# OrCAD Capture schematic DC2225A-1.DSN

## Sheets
1 PAGE3: size Custom; title: HIGH EFFICIENCY, SINGLE-OUTPUT SYNCHRONOUS BUCK; rev: 1; company: TM
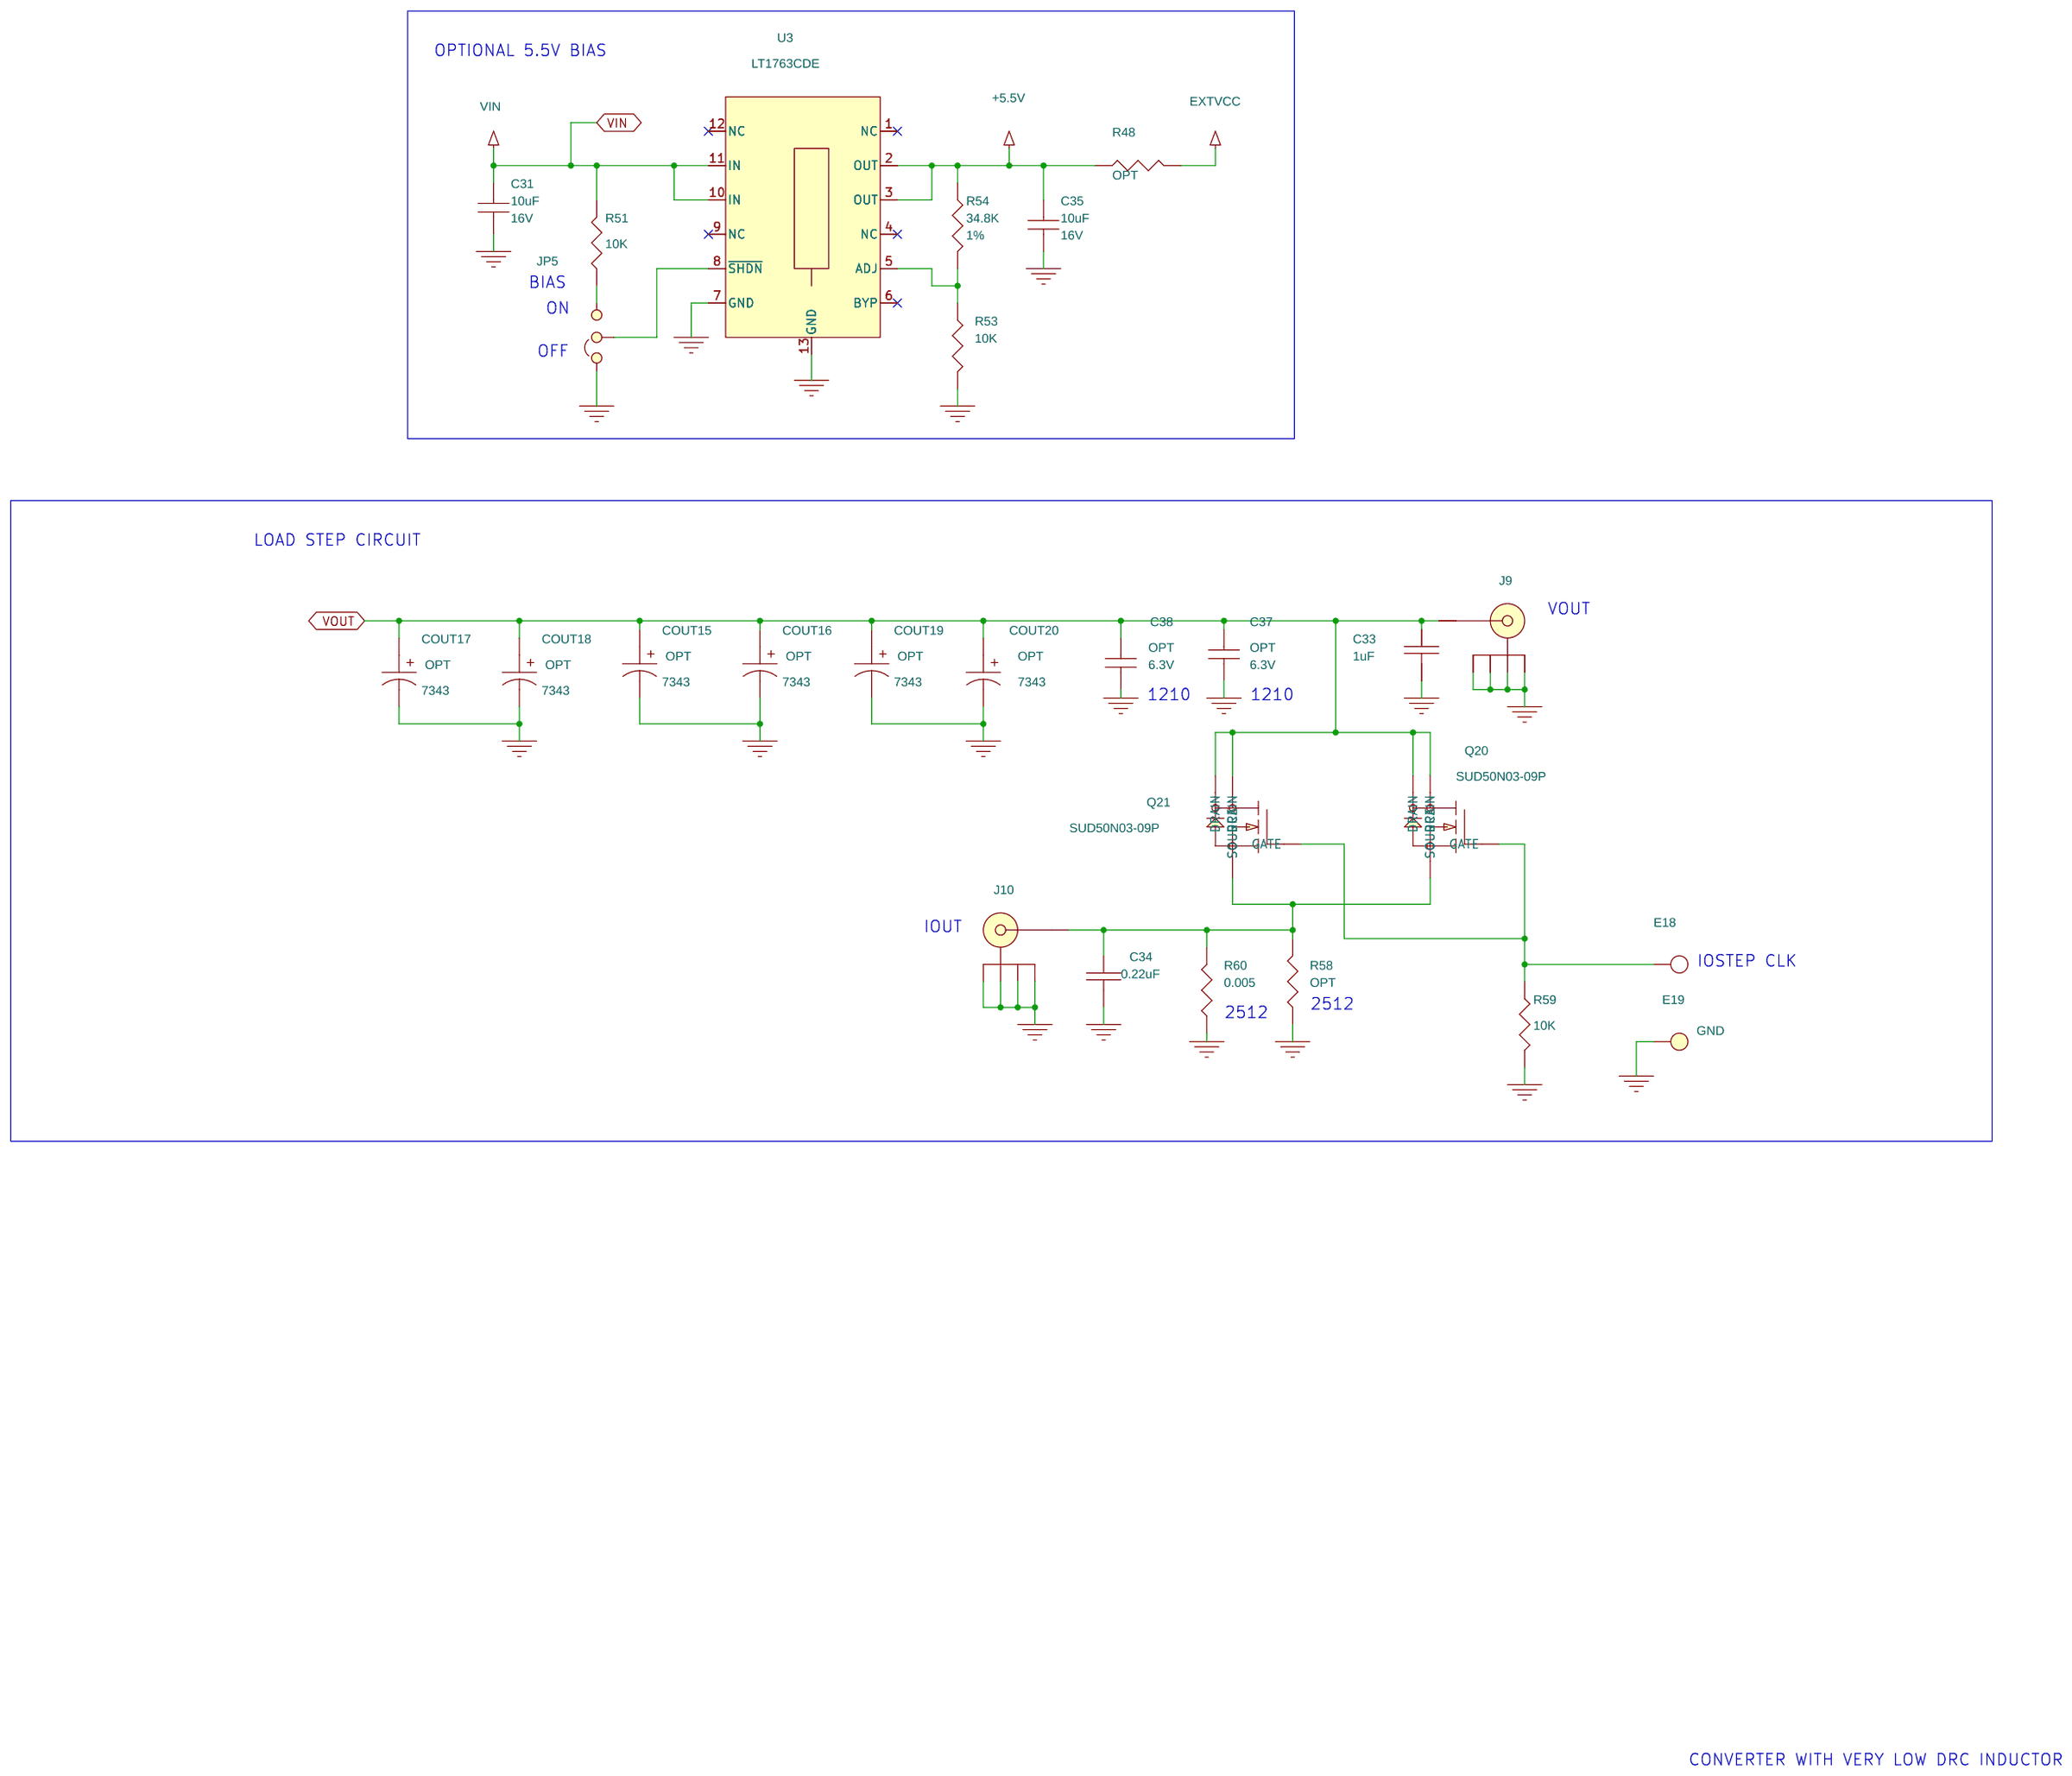
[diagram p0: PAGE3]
2 PAGE2: size Custom
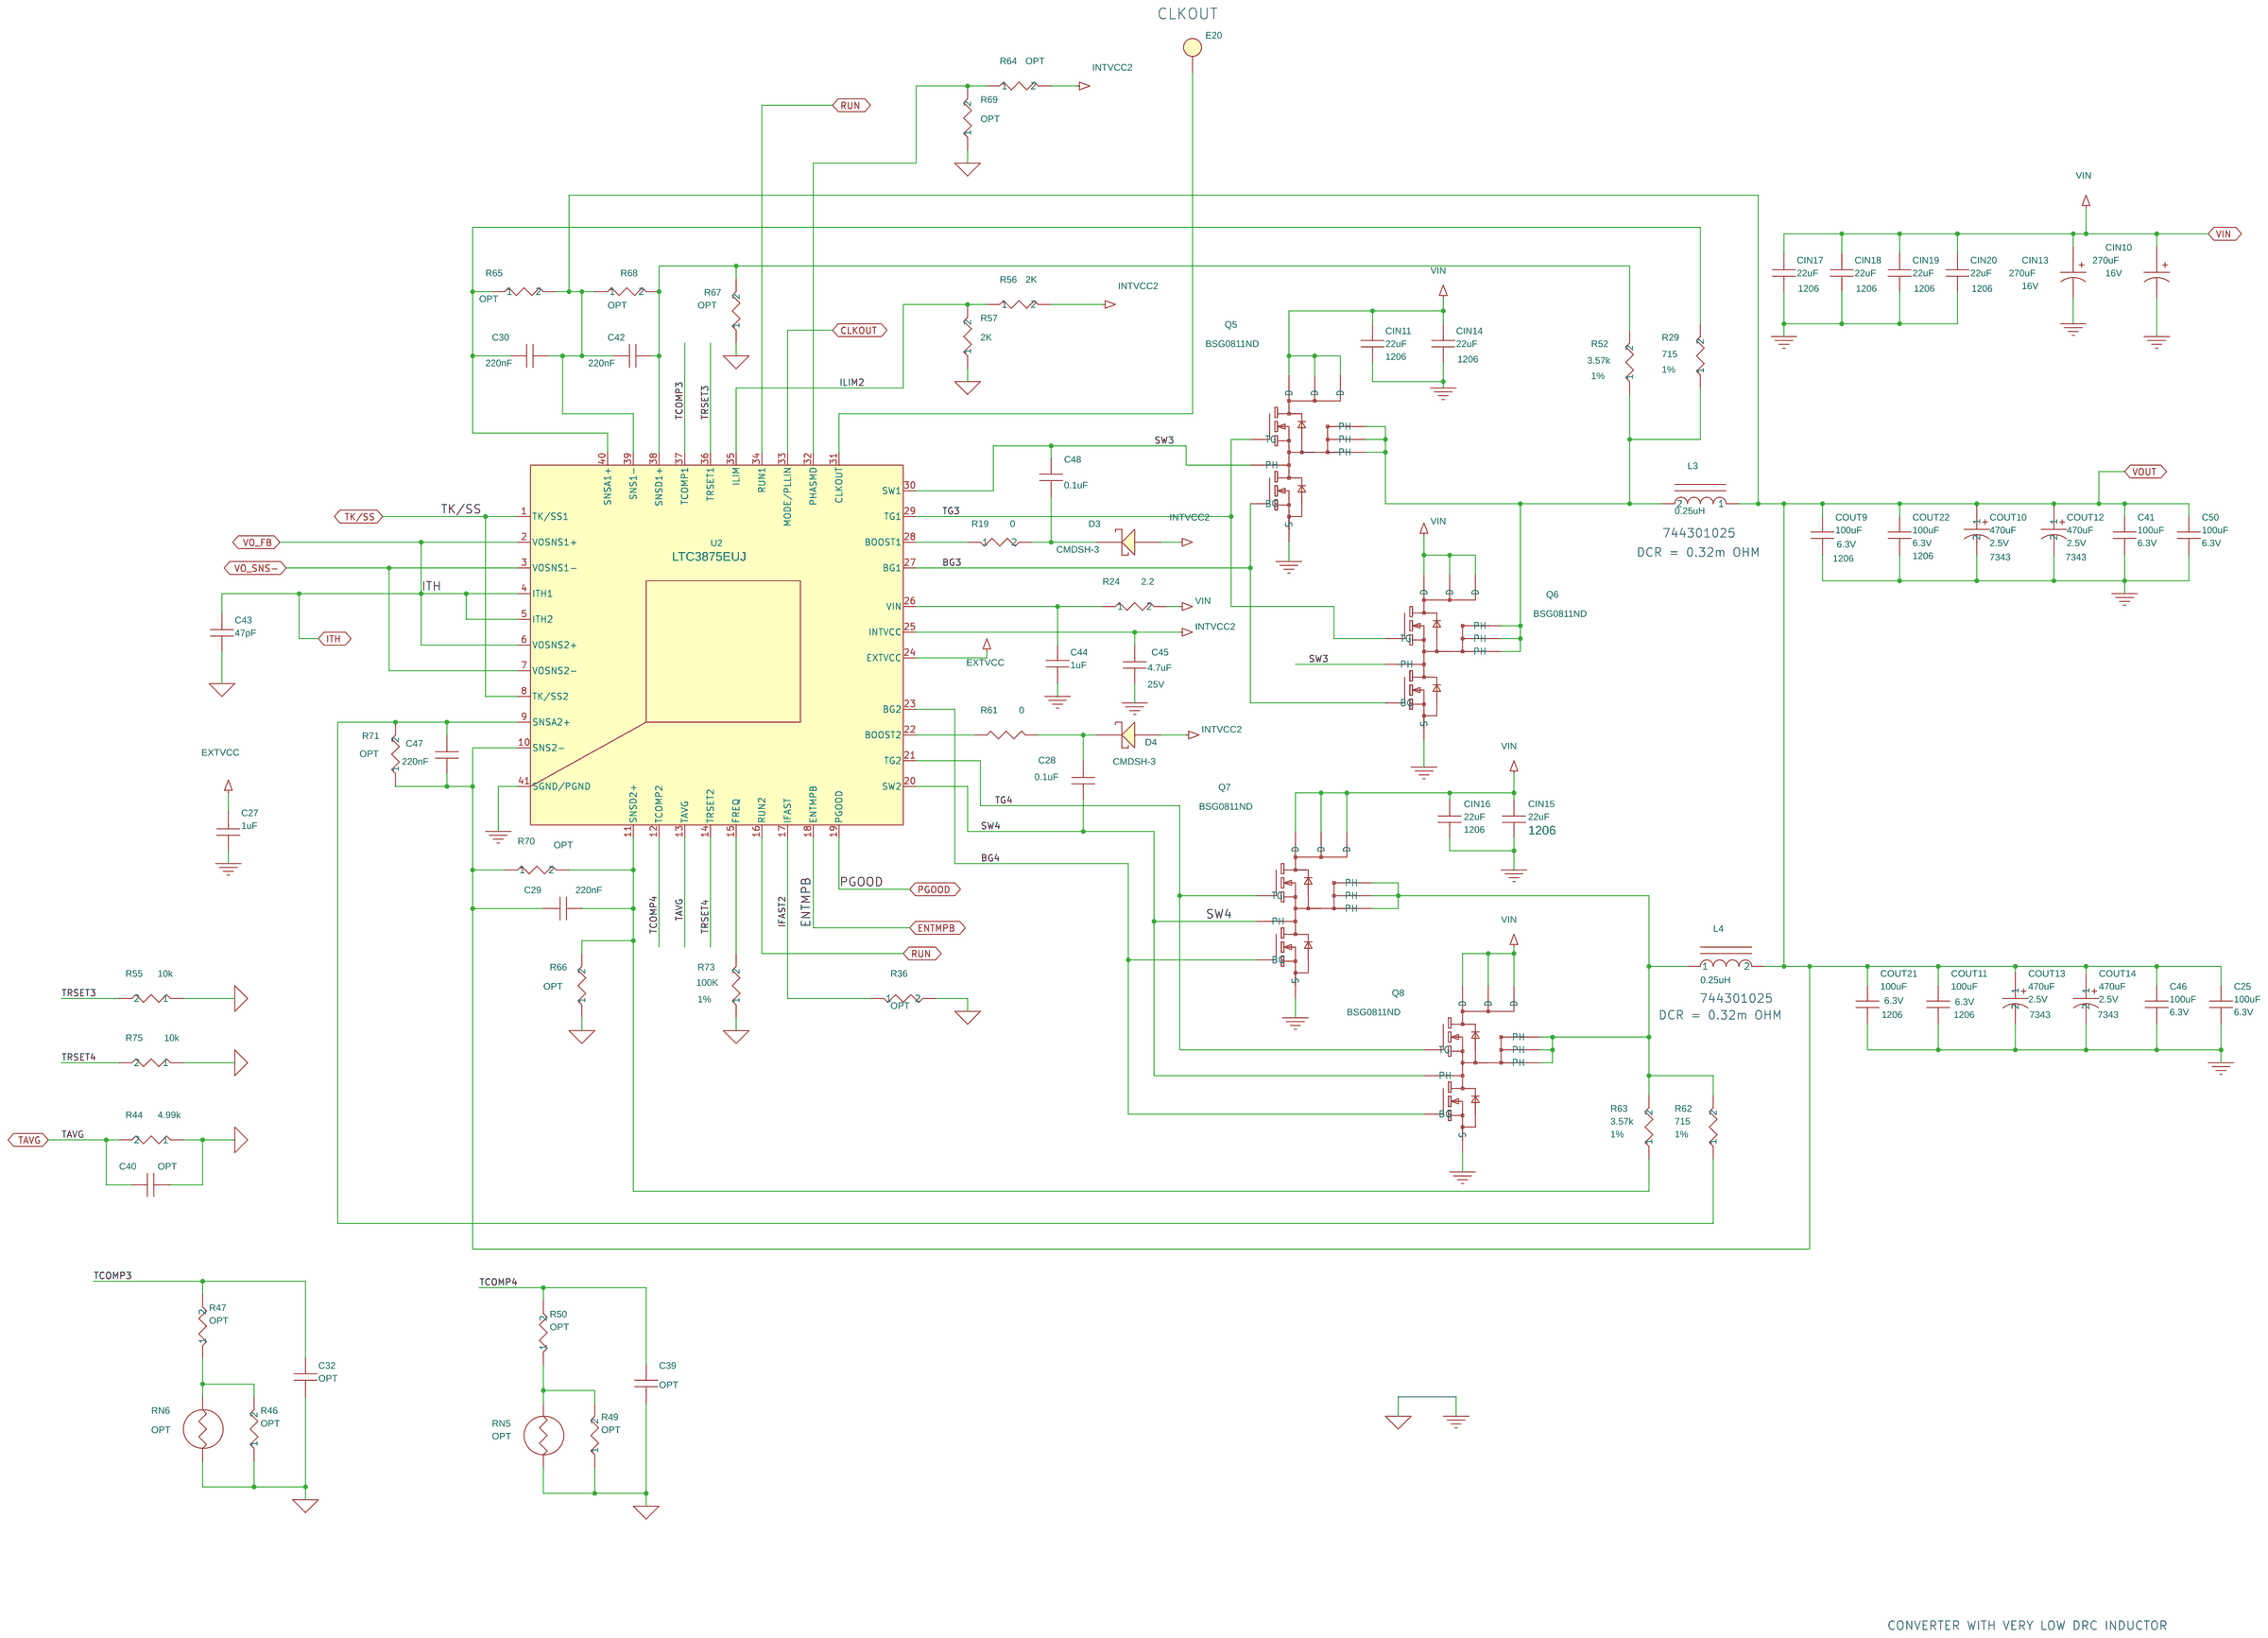
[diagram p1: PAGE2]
3 PAGE1: size Custom
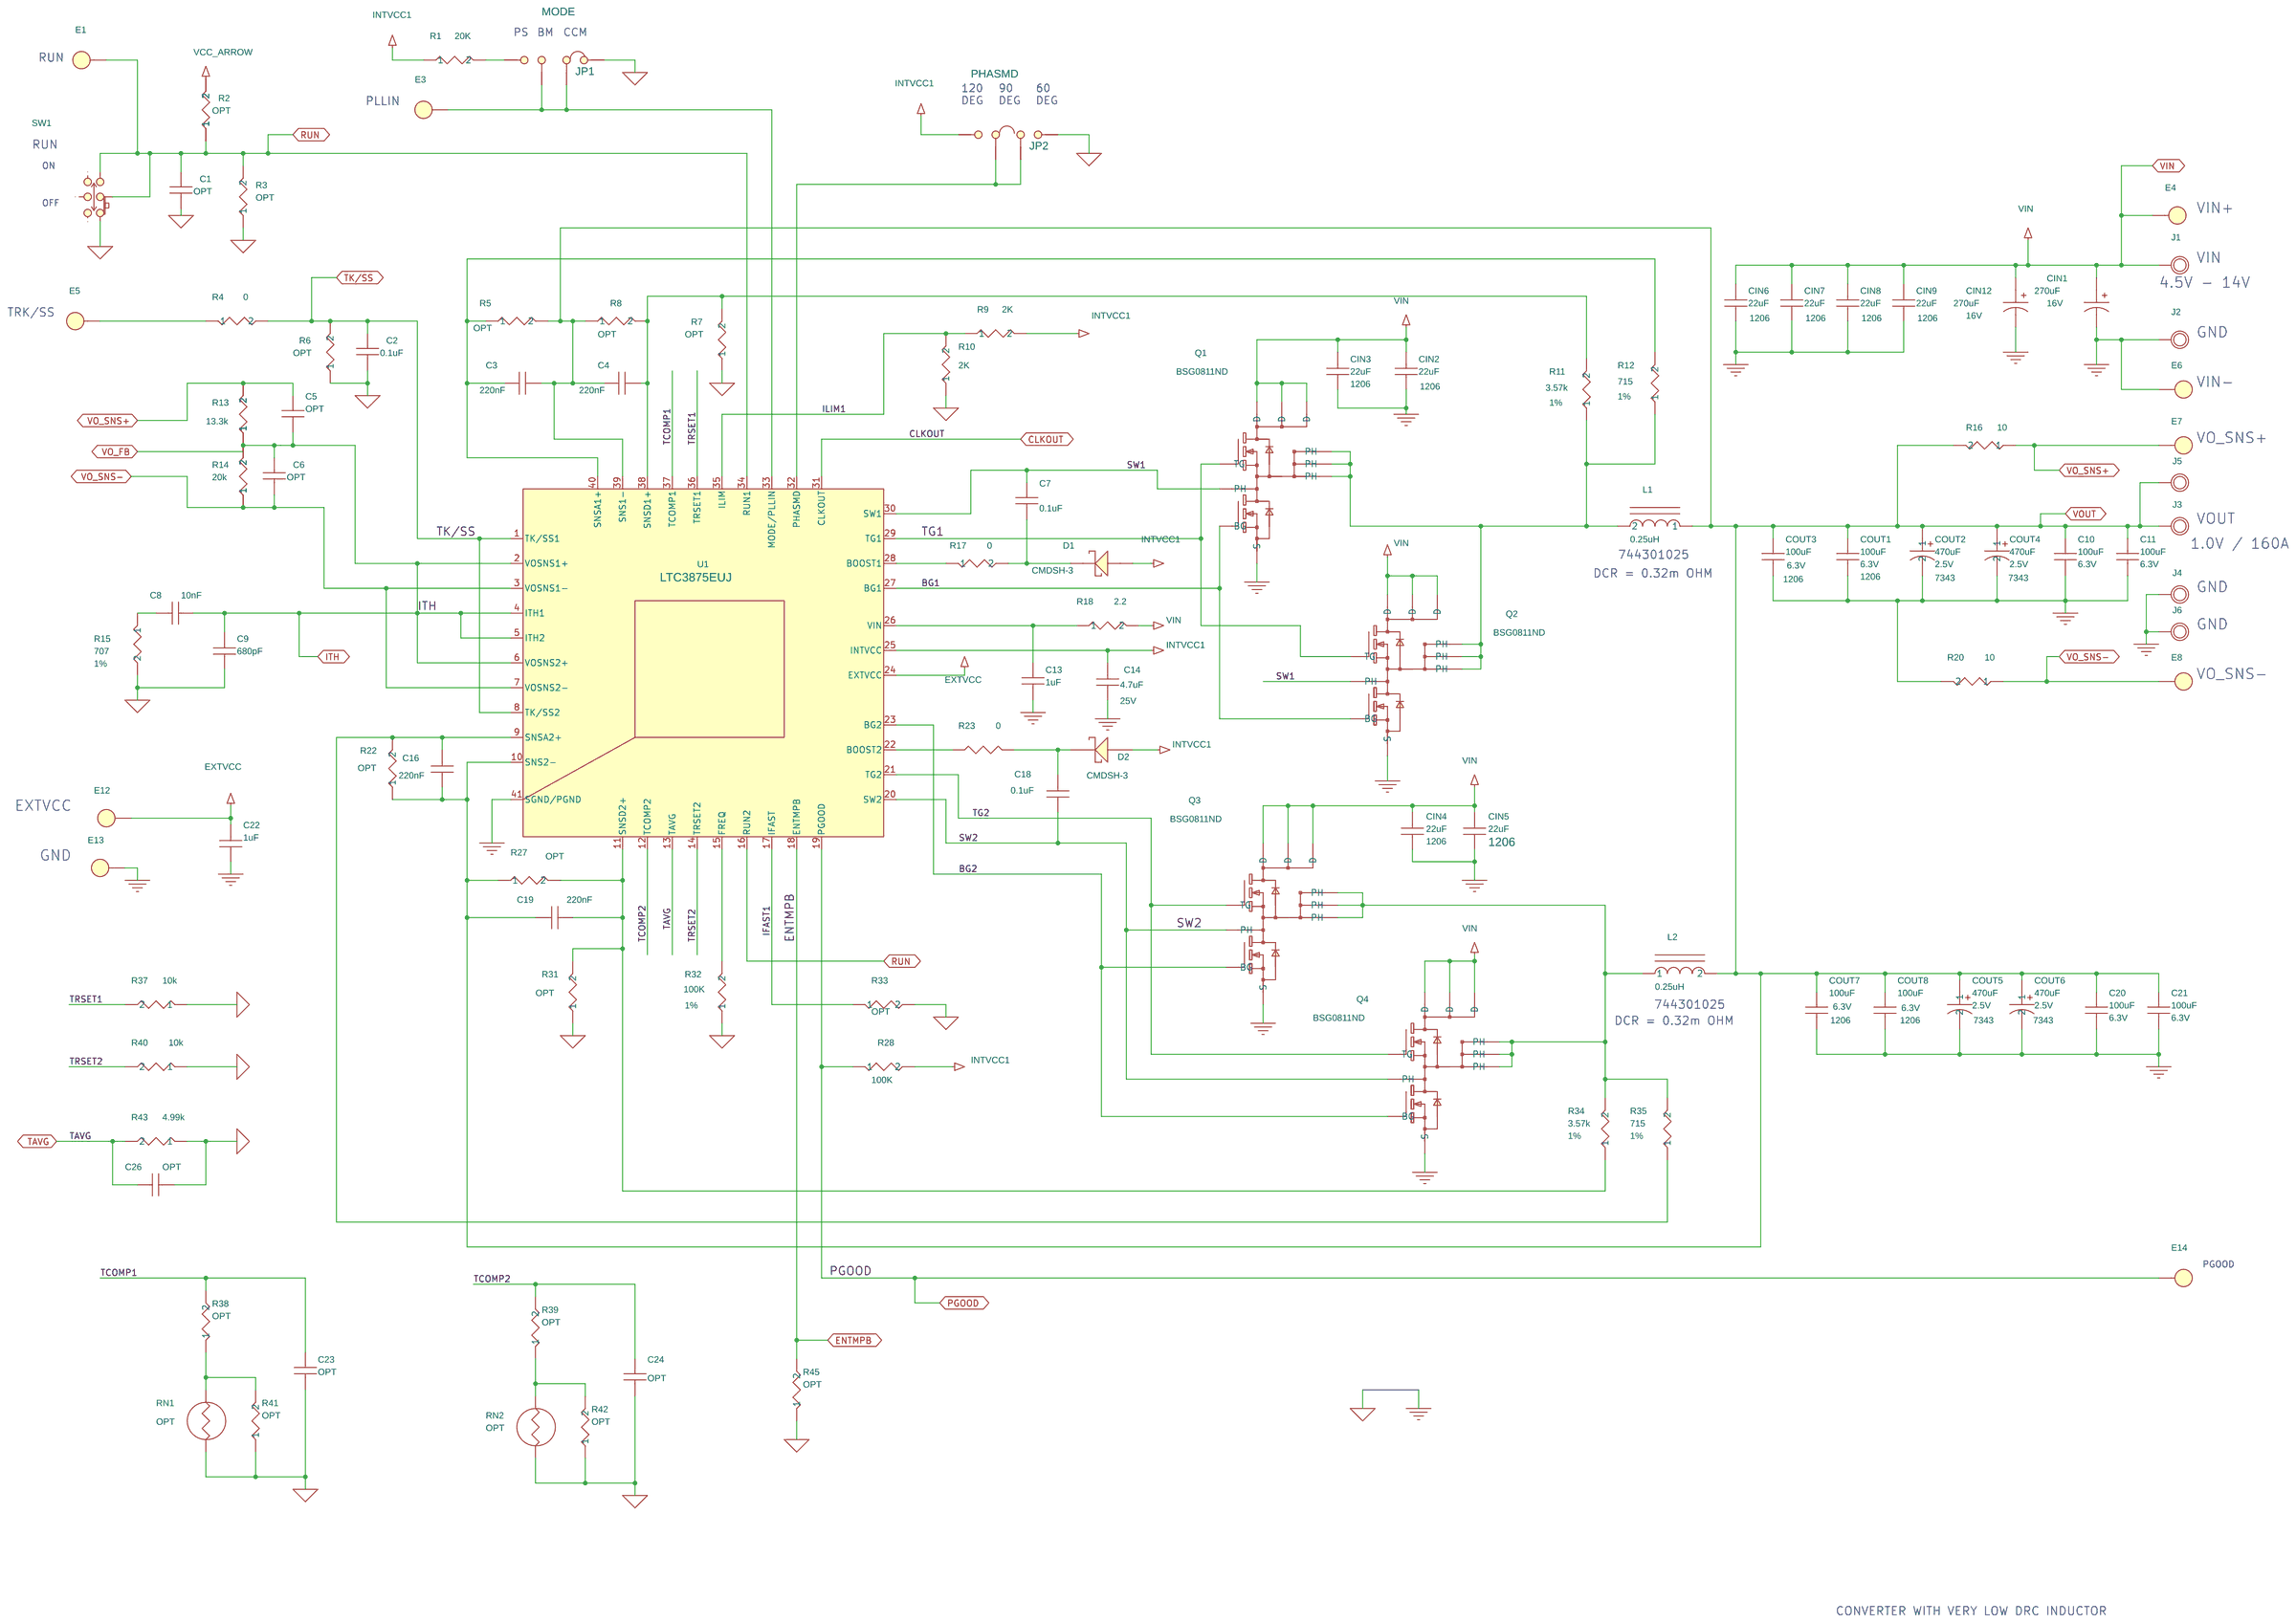
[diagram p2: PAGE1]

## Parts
sheet PAGE1
C1  OPT  [0603]
C2  0.1uF  [0603]
C3  220nF  [0603]
C4  220nF  [0603]
C5  OPT  [0603]
C6  OPT  [0603]
C7  0.1uF  [0603]
C8  10nF  [0603]
C9  680pF  [0603]
C10  100uF  [1210]
C11  100uF  [1210]
C13  1uF  [0603]
C14  4.7uF  [0805]
C16  220nF  [0603]
C18  0.1uF  [0603]
C19  220nF  [0603]
C20  100uF  [1210]
C21  100uF  [1210]
C22  1uF  [0603]
C23  OPT  [0603]
C24  OPT  [0603]
C26  OPT  [0603]
CIN1  270uF  [sanyo-E12]
CIN2  22uF  [1206]
CIN3  22uF  [1206]
CIN4  22uF  [1206]
CIN5  22uF  [1206]
CIN6  22uF  [1206]
CIN7  22uF  [1206]
CIN8  22uF  [1206]
CIN9  22uF  [1206]
CIN12  270uF  [sanyo-E12]
COUT1  100uF  [1206]
COUT2  470uF  [7343]
COUT3  100uF  [1206]
COUT4  470uF  [7343]
COUT5  470uF  [7343]
COUT6  470uF  [7343]
COUT7  100uF  [1206]
COUT8  100uF  [1206]
D1  CMDSH-3  [SOD-323]
D2  CMDSH-3  [SOD-323]
E1  E  [TURRETS]
E3  VIN  [TURRETS]
E4  VIN  [TURRETS]
E5  E  [TURRETS]
E6  VIN  [TURRETS]
E7  VIN  [TURRETS]
E8  VIN  [TURRETS]
E12  VIN  [TURRETS]
E13  VIN  [TURRETS]
E14  VIN  [TURRETS]
J1  GND  [CON\LUG\10]
J2  GND  [CON\LUG\10]
J3  GND  [CON\LUG\10]
J4  GND  [CON\LUG\10]
J5  GND  [CON\LUG\10]
J6  GND  [CON\LUG\10]
JP1  MODE  [SIP-4P]
JP2  PHASMD  [SIP-4P]
L1  0.25uH  [7443010-25/33]
L2  0.25uH  [7443010-25/33]
Q1  BSG0811ND  [PG-TISON8-4]
Q2  BSG0811ND  [PG-TISON8-4]
Q3  BSG0811ND  [PG-TISON8-4]
Q4  BSG0811ND  [PG-TISON8-4]
R1  20K  [0603]
R2  OPT  [0603]
R3  OPT  [0603]
R4  0  [0603]
R5  OPT  [0603]
R6  OPT  [0603]
R7  OPT  [0603]
R8  OPT  [0603]
R9  2K  [0603]
R10  2K  [0603]
R11  3.57k  [0603]
R12  715  [0603]
R13  13.3k  [0603]
R14  20k  [0603]
R15  707  [0603]
R16  10  [0603]
R17  0  [0603]
R18  2.2  [0603]
R20  10  [0603]
R22  OPT  [0603]
R23  0  [0603]
R27  OPT  [0603]
R28  100K  [0603]
R31  OPT  [0603]
R32  100K  [0603]
R33  OPT  [0603]
R34  3.57k  [0603]
R35  715  [0603]
R37  10k  [0603]
R38  OPT  [0603]
R39  OPT  [0603]
R40  10k  [0603]
R41  OPT  [0603]
R42  OPT  [0603]
R43  4.99k  [0603]
R45  OPT  [0603]
RN1  OPT  [0603]
RN2  OPT  [0603]
SW1  JP3X1/079\NO\12  [JS202011]
U1  LTC3875EUJ  [UJ-40-QFN(6X6MM)]
XJP1  SHUNT  [NONE]
XJP2  SHUNT  [NONE]
sheet PAGE2
C25  100uF  [1210]
C27  1uF  [0603]
C28  0.1uF  [0603]
C29  220nF  [0603]
C30  220nF  [0603]
C32  OPT  [0603]
C39  OPT  [0603]
C40  OPT  [0603]
C41  100uF  [1210]
C42  220nF  [0603]
C43  47pF  [0603]
C44  1uF  [0603]
C45  4.7uF  [0805]
C46  100uF  [1210]
C47  220nF  [0603]
C48  0.1uF  [0603]
C50  100uF  [1210]
CIN10  270uF  [sanyo-E12]
CIN11  22uF  [1206]
CIN13  270uF  [sanyo-E12]
CIN14  22uF  [1206]
CIN15  22uF  [1206]
CIN16  22uF  [1206]
CIN17  22uF  [1206]
CIN18  22uF  [1206]
CIN19  22uF  [1206]
CIN20  22uF  [1206]
COUT9  100uF  [1206]
COUT10  470uF  [7343]
COUT11  100uF  [1206]
COUT12  470uF  [7343]
COUT13  470uF  [7343]
COUT14  470uF  [7343]
COUT21  100uF  [1206]
COUT22  100uF  [1206]
D3  CMDSH-3  [SOD-323]
D4  CMDSH-3  [SOD-323]
E20  VIN  [TURRETS]
L3  0.25uH  [7443010-25/33]
L4  0.25uH  [7443010-25/33]
Q5  BSG0811ND  [PG-TISON8-4]
Q6  BSG0811ND  [PG-TISON8-4]
Q7  BSG0811ND  [PG-TISON8-4]
Q8  BSG0811ND  [PG-TISON8-4]
R19  0  [0603]
R24  2.2  [0603]
R29  715  [0603]
R36  OPT  [0603]
R44  4.99k  [0603]
R46  OPT  [0603]
R47  OPT  [0603]
R49  OPT  [0603]
R50  OPT  [0603]
R52  3.57k  [0603]
R55  10k  [0603]
R56  2K  [0603]
R57  2K  [0603]
R61  0  [0603]
R62  715  [0603]
R63  3.57k  [0603]
R64  OPT  [0603]
R65  OPT  [0603]
R66  OPT  [0603]
R67  OPT  [0603]
R68  OPT  [0603]
R69  OPT  [0603]
R70  OPT  [0603]
R71  OPT  [0603]
R73  100K  [0603]
R75  10k  [0603]
RN5  OPT  [0603]
RN6  OPT  [0603]
U2  LTC3875EUJ  [UJ-40-QFN(6X6MM)]
sheet PAGE3
C31  10uF  [1210]
C33  1uF  [0805]
C34  0.22uF  [0805]
C35  10uF  [1210]
C37  OPT  [1210]
C38  OPT  [1210]
COUT15  OPT  [7343]
COUT16  OPT  [7343]
COUT17  OPT  [7343]
COUT18  OPT  [7343]
COUT19  OPT  [7343]
COUT20  OPT  [7343]
E18  SDA  [TURRETS]
E19  GND  [TURRETS]
J9  XXX  [BNC]
J10  XXX  [BNC]
JP5  JP3X1/079\NO\12  [HD1X3-079]
Q20  SUD50N03-09P  [TO-252]
Q21  SUD50N03-09P  [TO-252]
R48  OPT  [0603]
R51  10K  [0603]
R53  10K  [0603]
R54  34.8K  [0603]
R58  OPT  [2512]
R59  10K  [0603]
R60  0.005  [2512]
U3  LT1763CDE  [DE/UE_12_4mmx3mm]

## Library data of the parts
C1 = CAP_NP_1_13: CAP, 0603 OPTION; Part Number: OPTION
C2 = CAP_NP_1_20: CAP, 0603 0.1uF 10% 25V X7R; Part Number: TDK C1608X7R1E104K
C3 = CAP_NP_1_16: CAP, 0603 1nF 10% 50V X7R; Part Number: AVX 06035C102KAT
C4 = CAP_NP_1_4: CAP, 0603 1nF 10% 50V X7R; Part Number: AVX 06035C102KAT
C5 = CAP_NP_1_19: CAP, 0603 0.1uF 10% 25V X7R; Part Number: TDK C1608X7R1E104K
C6 = CAP_NP_1_11: CAP, 0603 0.1uF 10% 25V X7R; Part Number: TDK C1608X7R1E104K
C7 C48 = CAP_NP_1_3: CAP, 0603 0.1uF 10% 25V X7R; Part Number: TDK C1608X7R1E104K
C8 = CAP_NP_1_7: CAP, 0603 1nF 10% 50V X7R; Part Number: AVX 06035C102KAT
C9 C43 = CAP_NP_4: CAP, 0603 150pF 10% 25V X7R; Part Number: AVX 06033C151KAT2A
C10 C11 C20 C21 C25 C41 C46 C50 = CAP_NP_4: CAP, 0805 10uF 10% 10V X5R; Part Number: MURATA GRM21BR61A106KE19; Voltage: 6.3V
C13 = CAP_NP_1_12: CAP, 0603 1uF 10% 16V X5R; Part Number: AVX 0603YD105KAT
C14 C45 = CAP_NP_3: CAP, 0805 4.7uF 10% 10V X5R; Part Number: TAIYO YUDEN LMK212BJ475KG-T; Voltage: 25V
C16 = CAP_NP_1_15: CAP, 0603 1nF 10% 50V X7R; Part Number: AVX 06035C102KAT
C18 = CAP_NP_1_18: CAP, 0603 0.1uF 10% 25V X7R; Part Number: TDK C1608X7R1E104K
C19 = CAP_NP_1_5: CAP, 0603 1nF 10% 50V X7R; Part Number: AVX 06035C102KAT
C22 = CAP_NP_1: CAP, 0603 1uF 10% 16V X5R; Part Number: AVX 0603YD105KAT
C23 = CAP_NP_1_9: CAP, 0603 OPTION; Part Number: OPTION
C24 = CAP_NP_1_6: CAP, 0603 OPTION; Part Number: OPTION
C26 = CAP_NP_1_2: CAP, 0603 OPTION; Part Number: OPTION
CIN1 CIN10 CIN12 CIN13 = CAP_POL: CAP, 270uF 20% 16V OSCON; Field1: OPT; Part Number: SANYO OSCON 16SVPC270M; Voltage: 16V
CIN2 = CAP_NP_1_1: CAP, 1210 OPTION; Part Number: OPTION
CIN3 = CAP_NP_1_10: CAP, 1210 10uF 10% 25V X5R; Part Number: MURATA GRM32DR61E106KA12L
CIN4 CIN16 = CAP_NP_1_14: CAP, 1210 10uF 10% 25V X5R; Part Number: MURATA GRM32DR61E106KA12L
CIN5 CIN20 = CAP_NP_1_17: CAP, 1210 OPTION; Part Number: OPTION
CIN6 = CAP_NP_1_8: CAP, 1210 OPTION; Part Number: OPTION
CIN7 = CAP_NP_1_23: CAP, 1210 OPTION; Part Number: OPTION
CIN8 = CAP_NP_1_22: CAP, 1210 OPTION; Part Number: OPTION
CIN9 = CAP_NP_1_21: CAP, 1210 OPTION; Part Number: OPTION
COUT1 COUT3 COUT7-COUT9 COUT11 COUT21 COUT22 = CAP_NP_4: CAP, 1206 100uF 20% 6.3V X5R; Part Number: MURATA GRM31CR60J107M339L; Voltage: 6.3V
COUT2 COUT13 = tant_1: CAP, 7343 330uF 20% 2.5V POSCAP; Part Number: SANYO 2R5TPE330M9; Voltage: 2.5V
COUT4 COUT10 = tant_3: CAP, 7343 330uF 20% 2.5V POSCAP; Part Number: SANYO 2R5TPE330M9; Voltage: 2.5V
COUT5 COUT12 = tant_2: CAP, 7343 330uF 20% 2.5V POSCAP; Part Number: SANYO 2R5TPE330M9; Voltage: 2.5V
COUT6 COUT14 = tant: CAP, 7343 330uF 20% 2.5V POSCAP; Part Number: SANYO 2R5TPE330M9; Voltage: 2.5V
D1-D4 = D-SCHOTTKY_0: DIODE,CMDSH-3 SOD323; Field1: SOD323; Part Number: CENTRAL CMDSH-3TR
E1 E3-E8 E12-E14 E20 = E_0: TURRET; Part Number: MILL-MAX 2501-2-00-80-00-00-07-0
J1-J6 = TP_KEY_1502-2_0: JACK, BANANA; Part Number: KEYSTONE 575-4
JP1 JP2 = JMPR3_0: HEADER, 4PIN; Part Number: SAMTEC TMM-104-02--L-S
L1 L3 = INDUCTOR_IRON_1: IND, 0.4uH
L2 L4 = INDUCTOR_IRON: IND, 0.4uH
Q1-Q8 = FDMS3610S_3: XSTR, POWER MOSFET; Part Number: FAIRCHILD FDMS3610S
R1 = R_10: RES, 0603 20K OHMS 1% 1/10W; Part Number: VISHAY CRCW060320K0FKEA
R2 R50 = R_11: RES, 0603 OPTION; Part Number: OPTION
R3 = R_26: RES, 0603 OPTION; Part Number: OPTION
R4 = R_9: RES, 0603 0 OHM JUMPER; Part Number: VISHAY CRCW06030000Z0EA
R5 R55 = R_19: RES, 0603 OPTION; Part Number: OPTION
R6 R69 = R_18: RES, 0603 OPTION; Part Number: OPTION
R7 = R_28: RES, 0603 100K OHMS 1% 1/10W; Part Number: VISHAY CRCW0603100KFKEA; Tol: 1%
R8 = R_27: RES, 0603 OPTION; Part Number: OPTION
R9 R46 = R_22: RES, 0603 OPTION; Part Number: OPTION
R10 = R_6: RES, 0603 OPTION; Part Number: OPTION
R11 = R_5: RES, 0603 100K OHMS 1% 1/10W; Part Number: VISHAY CRCW0603100KFKEA; Tol: 1%
R12 = R_33: RES, 0603 100K OHMS 1% 1/10W; Part Number: VISHAY CRCW0603100KFKEA; Tol: 1%
R13 = R_30: RES, 0603 OPTION; Part Number: OPTION
R14 = R_14: RES, 0603 OPTION; Part Number: OPTION
R15 = R_13: RES, 0603 18.2K OHMS 1% 1/10W; Part Number: AAC CR16-1822FM; Tol: 1%
R16 = R_8: RES, 0603 10 OHMS 5% 1/10W; Part Number: VISHAY CRCW060310R0JNEA
R17 = R_12: RES, 0603 0 OHM JUMPER; Part Number: VISHAY CRCW06030000Z0EA
R18 = R_29: RES, 0603 2.2 OHMS 5% 1/10W; Part Number: VISHAY CRCW06032R20JNEA
R20 = R_31: RES, 0603 10 OHMS 5% 1/10W; Part Number: VISHAY CRCW060310R0JNEA
R22 = R_34: RES, 0603 OPTION; Part Number: OPTION
R23 R61 = RES_0: RES, 0603 0 OHM JUMPER; Part Number: VISHAY CRCW06030000Z0EA
R27 R68 = R_15: RES, 0603 OPTION; Part Number: OPTION
R28 = R_25: RES, 0603 100K OHMS 1% 1/10W; Part Number: VISHAY CRCW0603100KFKEA; Tol: 1%
R29 R31 = R: RES, 0603 100K OHMS 1% 1/10W; Part Number: VISHAY CRCW0603100KFKEA; Tol: 1%
R32 R63 = R_20: RES, 0603 100K OHMS 1% 1/10W; Part Number: VISHAY CRCW0603100KFKEA; Tol: 1%
R33 = R_16: RES, 0603 100K OHMS 1% 1/10W; Part Number: VISHAY CRCW0603100KFKEA; Tol: 1%
R34 = R_7: RES, 0603 100K OHMS 1% 1/10W; Part Number: VISHAY CRCW0603100KFKEA; Tol: 1%
R35 = R_1: RES, 0603 100K OHMS 1% 1/10W; Part Number: VISHAY CRCW0603100KFKEA; Tol: 1%
R37 = R_32: RES, 0603 OPTION; Part Number: OPTION
R38 R49 = R_23: RES, 0603 OPTION; Part Number: OPTION
R39 R57 = R_24: RES, 0603 OPTION; Part Number: OPTION
R40 = R_3: RES, 0603 OPTION; Part Number: OPTION
R41 R56 = R_2: RES, 0603 OPTION; Part Number: OPTION
R42 R64 = R_4: RES, 0603 OPTION; Part Number: OPTION
R43 = R_17: RES, 0603 OPTION; Part Number: OPTION
R45 = R_21: RES, 0603 OPTION; Part Number: OPTION
RN1 RN2 RN5 RN6 = RNTC: THERMISTOR, OPTION; Part Number: OPTION
SW1 = JP3X1_079_NO_12_3
U1 = LTC1629_1: IC,; Part Number: LINEAR TECH. LTC3855EUJ
XJP1 XJP2 = SHUNT: SHUNT, 2mm; Part Number: SAMTEC 2SN-BK-G
C27 = CAP_NP_1_1: CAP, 0603 1uF 10% 16V X5R; Part Number: AVX 0603YD105KAT
C28 = CAP_NP_1_15: CAP, 0603 0.1uF 10% 25V X7R; Part Number: TDK C1608X7R1E104K
C29 = CAP_NP_1: CAP, 0603 1nF 10% 50V X7R; Part Number: AVX 06035C102KAT
C30 = CAP_NP_1_12: CAP, 0603 1nF 10% 50V X7R; Part Number: AVX 06035C102KAT
C32 = CAP_NP_1_5: CAP, 0603 OPTION; Part Number: OPTION
C39 = CAP_NP_1_4: CAP, 0603 OPTION; Part Number: OPTION
C40 = CAP_NP_1_16: CAP, 0603 OPTION; Part Number: OPTION
C42 = CAP_NP_1_2: CAP, 0603 1nF 10% 50V X7R; Part Number: AVX 06035C102KAT
C44 = CAP_NP_1_13: CAP, 0603 1uF 10% 16V X5R; Part Number: AVX 0603YD105KAT
C47 = CAP_NP_1_9: CAP, 0603 1nF 10% 50V X7R; Part Number: AVX 06035C102KAT
CIN11 = CAP_NP_1_8: CAP, 1210 10uF 10% 25V X5R; Part Number: MURATA GRM32DR61E106KA12L
CIN14 = CAP_NP_1_11: CAP, 1210 OPTION; Part Number: OPTION
CIN15 = CAP_NP_1_6: CAP, 1210 OPTION; Part Number: OPTION
CIN17 = CAP_NP_1_7: CAP, 1210 OPTION; Part Number: OPTION
CIN18 = CAP_NP_1_10: CAP, 1210 OPTION; Part Number: OPTION
CIN19 = CAP_NP_1_18: CAP, 1210 OPTION; Part Number: OPTION
R19 = R_16: RES, 0603 0 OHM JUMPER; Part Number: VISHAY CRCW06030000Z0EA
R24 = R_1: RES, 0603 2.2 OHMS 5% 1/10W; Part Number: VISHAY CRCW06032R20JNEA
R36 = R_10: RES, 0603 100K OHMS 1% 1/10W; Part Number: VISHAY CRCW0603100KFKEA; Tol: 1%
R44 = R_8: RES, 0603 OPTION; Part Number: OPTION
R47 = R_7: RES, 0603 OPTION; Part Number: OPTION
R52 = R_14: RES, 0603 100K OHMS 1% 1/10W; Part Number: VISHAY CRCW0603100KFKEA; Tol: 1%
R62 = R_6: RES, 0603 100K OHMS 1% 1/10W; Part Number: VISHAY CRCW0603100KFKEA; Tol: 1%
R65 = R_12: RES, 0603 OPTION; Part Number: OPTION
R66 = R_21: RES, 0603 100K OHMS 1% 1/10W; Part Number: VISHAY CRCW0603100KFKEA; Tol: 1%
R67 = R_17: RES, 0603 100K OHMS 1% 1/10W; Part Number: VISHAY CRCW0603100KFKEA; Tol: 1%
R70 = R_5: RES, 0603 OPTION; Part Number: OPTION
R71 = R_13: RES, 0603 OPTION; Part Number: OPTION
R73 = R_3: RES, 0603 100K OHMS 1% 1/10W; Part Number: VISHAY CRCW0603100KFKEA; Tol: 1%
R75 = R_9: RES, 0603 OPTION; Part Number: OPTION
U2 = LTC1629_0: IC,; Part Number: LINEAR TECH. LTC3855EUJ
C31 = CAP_NP_1: CAP, 1210 10uF 10% 16V X7R; Part Number: MURATA GRM32DR71C106KA01; Voltage: 16V
C33 C34 = CAP1206_1: Manufacturer: Kemet; Manufacturer P/N: C1206C106K8RACTU; Tolerance: 10%; Type: cer 1206 X7R; Vendor: Digikey; Vendor P/N: 399-4937-1-ND; Volts/Amps/Watts: 10V
C35 = CAP_NP_1_1: CAP, 1210 10uF 10% 16V X7R; Part Number: MURATA GRM32DR71C106KA01; Voltage: 16V
C37 C38 = CAP_NP_0: CAP, 1210 100uF 20% 6.3V X5R; Part Number: TDK C3225X5R0J107M; Voltage: 6.3V
COUT15-COUT20 = t510x337k010as: CAP, 7343 330uF 20% 2.5V POSCAP OPTION; 3rd Part Field: POSCAP; Part Number: SANYO 2R5TPE330M9 OPTION
E18 = TP_KEY_1502-2: TURRET; Part Number: MILL-MAX 2501-2-00-80-00-00-07-0
E19 = T_POINT_R_0: TURRET; Part Number: MILL-MAX 2501-2-00-80-00-00-07-0; STATUS: ?
J9 J10 = BNC5-SCH_0: CONN,BNC,5 PINS; Part Number: CONNEX 112404
JP5 = JP3X1_079_NO_12_2
Q20 Q21 = IRF540_0
R48 R51 = RESISTOR_1: RES 0603 OPTION; Part Number: OPTION
R53 R59 = RES_0: RES, 0603 10K OHMS 5% 1/10W; Part Number: VISHAY CRCE060310K0JNEA
R54 = RESISTOR_1: RES, 0603 30.1K OHM 1% 1/10W; Part Number: VISHAY CRCW060330K1FKEA; Tolerance: 1%
R58 R60 = RES_0: RES, 2512 0.005 OHM 5% 1W; Part Number: PANASONIC ERJ-M1WSJ5M0U
U3 = LT1763_0: IC, REGULATOR; Part Number: LINEAR TECH. LT1761ES5-SD

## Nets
+5.5V: C35.1 R48.1 R54.2 U3.2(OUT) U3.3(OUT)
GND: C10.1 C11.1 C13.2 C14.2 C20.1 C21.1 C22.1 C25.1 C27.1 C31.2 C33.2 C34.2 C35.2 C37.1 C38.1 C41.1 C44.2 C45.2 C46.1 C50.1 CIN1.2 CIN2.1 CIN3.1 CIN4.1 CIN5.1 CIN6.1 CIN7.1 CIN8.1 CIN9.1 CIN10.2 CIN11.1 CIN12.2 CIN13.2 CIN14.1 CIN15.1 CIN16.1 CIN17.1 CIN18.1 CIN19.1 CIN20.1 COUT1.1 COUT2.2 COUT3.1 COUT4.2 COUT5.2 COUT6.2 COUT7.1 COUT8.1 COUT9.1 COUT10.2 COUT11.1 COUT12.2 COUT13.2 COUT14.2 COUT15.2 COUT16.2 COUT17.2 COUT18.2 COUT19.2 COUT20.2 COUT21.1 COUT22.1 E6.1 E13.1 E19.1(TP) J2.1 J4.1 J6.1 J9.2 J9.3 J9.4 J9.5 J10.2 J10.3 J10.4 J10.5 JP5.1 Q1.10(S) Q2.10(S) Q3.10(S) Q4.10(S) Q5.10(S) Q6.10(S) Q7.10(S) Q8.10(S) R20.2 R53.1 R58.1 R59.1 R60.1 U1.41(SGND/PGND) U2.41(SGND/PGND) U3.7(GND) U3.13(GND)
GND_A: C1.2 C2.2 C9.2 C23.2 C24.2 C26.2 C32.2 C39.2 C40.2 C43.2 JP1.4 JP2.4 R3.1 R6.1 R7.1 R10.1 R15.2 R31.1 R32.1 R33.2 R36.2 R37.1 R40.1 R41.1 R42.1 R43.1 R44.1 R45.1 R46.1 R49.1 R55.1 R57.1 R66.1 R67.1 R69.1 R73.1 R75.1 RN1.1 RN2.1 RN5.1 RN6.1 SW1.3
VIN: C31.1 CIN1.1 CIN2.2 CIN3.2 CIN4.2 CIN5.2 CIN6.2 CIN7.2 CIN8.2 CIN9.2 CIN10.1 CIN11.2 CIN12.1 CIN13.1 CIN14.2 CIN15.2 CIN16.2 CIN17.2 CIN18.2 CIN19.2 CIN20.2 E4.1 J1.1 Q1.3(D) Q1.4(D) Q1.9(D) Q2.3(D) Q2.4(D) Q2.9(D) Q3.3(D) Q3.4(D) Q3.9(D) Q4.3(D) Q4.4(D) Q4.9(D) Q5.3(D) Q5.4(D) Q5.9(D) Q6.3(D) Q6.4(D) Q6.9(D) Q7.3(D) Q7.4(D) Q7.9(D) Q8.3(D) Q8.4(D) Q8.9(D) R2.2 R18.2 R24.2 R51.2 U3.10(IN) U3.11(IN)
BG1: Q1.8(BG) Q2.8(BG) U1.27(BG1)
BG2: Q3.8(BG) Q4.8(BG) U1.23(BG2)
BG3: Q5.8(BG) Q6.8(BG) U2.27(BG1)
BG4: Q7.8(BG) Q8.8(BG) U2.23(BG2)
CLKOUT: U1.31(CLKOUT) U2.33(MODE/PLLIN)
ENTMPB: R45.2 U1.18(ENTMPB) U2.18(ENTMPB)
EXTVCC: C22.2 C27.2 E12.1 R48.2 U1.24(EXTVCC) U2.24(EXTVCC)
IFAST1: R33.1 U1.17(IFAST)
IFAST2: R36.1 U2.17(IFAST)
ILIM1: R9.1 R10.2 U1.35(ILIM)
ILIM2: R56.1 R57.2 U2.35(ILIM)
INTVCC1: C14.1 D1.2 D2.2 JP2.1 R1.1 R9.2 R28.2 U1.25(INTVCC)
INTVCC2: C45.1 D3.2 D4.2 R56.2 R64.2 U2.25(INTVCC)
ITH: C8.1 C9.1 C43.1 U1.4(ITH1) U1.5(ITH2) U2.4(ITH1) U2.5(ITH2)
PGOOD: E14.1 R28.1 U1.19(PGOOD) U2.19(PGOOD)
RUN: C1.1 E1.1 R2.1 R3.2 SW1.1 SW1.2 U1.16(RUN2) U1.34(RUN1) U2.16(RUN2) U2.34(RUN1)
SW1: C7.1 Q1.2(PH) Q2.2(PH) U1.30(SW1)
SW2: C18.1 Q3.2(PH) Q4.2(PH) U1.20(SW2)
SW3: C48.1 Q5.2(PH) Q6.2(PH) U2.30(SW1)
SW4: C28.1 Q7.2(PH) Q8.2(PH) U2.20(SW2)
TAVG: C26.1 C40.1 R43.2 R44.2 U1.13(TAVG) U2.13(TAVG)
TCOMP1: C23.1 R38.2 U1.37(TCOMP1)
TCOMP2: C24.1 R39.2 U1.12(TCOMP2)
TCOMP3: C32.1 R47.2 U2.37(TCOMP1)
TCOMP4: C39.1 R50.2 U2.12(TCOMP2)
TG1: Q1.1(TG) Q2.1(TG) U1.29(TG1)
TG2: Q3.1(TG) Q4.1(TG) U1.21(TG2)
TG3: Q5.1(TG) Q6.1(TG) U2.29(TG1)
TG4: Q7.1(TG) Q8.1(TG) U2.21(TG2)
TK/SS: C2.1 R4.2 R6.2 U1.1(TK/SS1) U1.8(TK/SS2) U2.1(TK/SS1) U2.8(TK/SS2)
TRSET1: R37.2 U1.36(TRSET1)
TRSET2: R40.2 U1.14(TRSET2)
TRSET3: R55.2 U2.36(TRSET1)
TRSET4: R75.2 U2.14(TRSET2)
VO_FB: C5.2 C6.1 R13.1 R14.2 U1.2(VOSNS1+) U1.6(VOSNS2+) U2.2(VOSNS1+) U2.6(VOSNS2+)
VO_SNS+: C5.1 E7.1 R13.2 R16.1
VO_SNS-: C6.2 E8.1 R14.1 R20.1 U1.3(VOSNS1-) U1.7(VOSNS2-) U2.3(VOSNS1-) U2.7(VOSNS2-)
VOUT: C3.2 C4.1 C10.2 C11.2 C16.1 C19.2 C20.2 C21.2 C25.2 C29.2 C30.2 C33.1 C37.2 C38.2 C41.2 C42.1 C46.2 C47.1 C50.2 COUT1.2 COUT2.1 COUT3.2 COUT4.1 COUT5.1 COUT6.1 COUT7.2 COUT8.2 COUT9.2 COUT10.1 COUT11.2 COUT12.1 COUT13.1 COUT14.1 COUT15.1 COUT16.1 COUT17.1 COUT18.1 COUT19.1 COUT20.1 COUT21.2 COUT22.2 J3.1 J5.1 J9.1 L1.1 L2.2 L3.1 L4.2 Q20.2(DRAIN) Q20.4(DRAIN) Q21.2(DRAIN) Q21.4(DRAIN) R5.2 R8.1 R16.2 R22.1 R27.1 R65.2 R68.1 R70.1 R71.1 U1.10(SNS2-) U1.39(SNS1-) U2.10(SNS2-) U2.39(SNS1-)
N18499535: C16.2 R22.2 R35.1 U1.9(SNSA2+)
N18499596: JP2.2 JP2.3 U1.32(PHASMD)
N18499680: C4.2 R7.2 R8.2 R11.2 U1.38(SNSD1+)
N18499846: C3.1 R5.1 R12.2 U1.40(SNSA1+)
N18499884: E3.1 JP1.2 JP1.3 U1.33(MODE/PLLIN)
N18500024: L2.1 Q3.5(PH) Q3.6(PH) Q3.7(PH) Q4.5(PH) Q4.6(PH) Q4.7(PH) R34.2 R35.2
N18500049: L1.2 Q1.5(PH) Q1.6(PH) Q1.7(PH) Q2.5(PH) Q2.6(PH) Q2.7(PH) R11.1 R12.1
N18500100: C13.1 R18.1 U1.26(VIN)
N18500116: C7.2 D1.1 R17.2
N18500316: R32.2 U1.15(FREQ)
N18500350: R39.1 R42.2 RN2.2
N18500413: R38.1 R41.2 RN1.2
N18500532: C19.1 R27.2 R31.2 R34.1 U1.11(SNSD2+)
N18500705: R17.1 U1.28(BOOST1)
N18500984: R23.1 U1.22(BOOST2)
N18501735: JP1.1 R1.2
N18501859: E5.1 R4.1
N19648852: C8.2 R15.1
N19672587: C18.2 D2.1 R23.2
N19749864: E18.1 Q20.1(GATE) Q21.1(GATE) R59.2
N19749875: C34.1 J10.1 Q20.3(SOURCE) Q21.3(SOURCE) R58.2 R60.2
N19755840: L4.1 Q7.5(PH) Q7.6(PH) Q7.7(PH) Q8.5(PH) Q8.6(PH) Q8.7(PH) R62.2 R63.2
N19755930: C47.2 R62.1 R71.2 U2.9(SNSA2+)
N19756055: C42.2 R52.2 R67.2 R68.2 U2.38(SNSD1+)
N19756133: C30.1 R29.2 R65.1 U2.40(SNSA1+)
N19756270: L3.2 Q5.5(PH) Q5.6(PH) Q5.7(PH) Q6.5(PH) Q6.6(PH) Q6.7(PH) R29.1 R52.1
N19756315: C44.1 R24.1 U2.26(VIN)
N19756325: C48.2 D3.1 R19.2
N19756400: E20.1 U2.31(CLKOUT)
N19756465: R73.2 U2.15(FREQ)
N19756508: R49.2 R50.1 RN5.2
N19756565: R46.2 R47.1 RN6.2
N19756686: C29.1 R63.1 R66.2 R70.2 U2.11(SNSD2+)
N19756800: R19.1 U2.28(BOOST1)
N19756961: R61.1 U2.22(BOOST2)
N19757925: C28.2 D4.1 R61.2
N19844066: R53.2 R54.1 U3.5(ADJ)
N19844101: JP5.3 R51.1
N19844103: JP5.2 U3.8(~{SHDN})
N19848129: R64.1 R69.2 U2.32(PHASMD)

Not connected (* = marked no-connect by the designer): SW1 4 5 6; U3 1(NC)* 4(NC)* 6(BYP)* 9(NC)* 12(NC)*

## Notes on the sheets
sheet 1
- OPTIONAL 5.5V BIAS
- BIAS
- ON
- OFF
- LOAD STEP CIRCUIT
- VOUT
- 1210
- 1210
- IOUT
- IOSTEP CLK
- 2512
- 2512
- CONVERTER WITH VERY LOW DRC INDUCTOR
sheet 2
- CLKOUT
- 744301025
- DCR = 0.32m OHM
- 744301025
- DCR = 0.32m OHM
- CONVERTER WITH VERY LOW DRC INDUCTOR
sheet 3
- PS
- BM
- CCM
- RUN
- PLLIN
- 120
  DEG
- 90
  DEG
- 60
  DEG
- RUN
- ON
- OFF
- VIN+
- VIN
- 4.5V - 14V
- TRK/SS
- GND
- VIN-
- VO_SNS+
- VOUT
- 1.0V / 160A
- 744301025
- DCR = 0.32m OHM
- GND
- GND
- VO_SNS-
- EXTVCC
- GND
- 744301025
- DCR = 0.32m OHM
- PGOOD
- CONVERTER WITH VERY LOW DRC INDUCTOR
